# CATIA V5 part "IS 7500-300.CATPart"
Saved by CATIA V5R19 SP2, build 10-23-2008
Part number: IS 7500-300
Bounding box of the stored display mesh (mm): x -74.81 to 74.81, y -74.81 to 74.81, z 0 to 755
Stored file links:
  C:\Users\Bora\Desktop\3D Katı model\IS serisi\IS 7500\IS 7500-300.CATPart
  C:\Program Files\Dassault Systemes\B19\intel_a\reffiles\standard\MetricThinPitch.txt
  C:\Program Files\Dassault Systemes\B19\intel_a\reffiles\standard\MetricThickPitch.txt
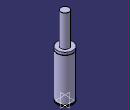
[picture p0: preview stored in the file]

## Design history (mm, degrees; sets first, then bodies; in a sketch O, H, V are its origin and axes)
Body1 (main body)
  Sketch1 on yz-plane, origin (0, 0, 0), H (0, 1, 0), V (0, 0, 1)
    point P1 (75, 430)
    point P2 (75, 425)
    point P5 (40, 754)
    point P7 (40, 754)
    point P12 (75, 425)
    point P13 (75, 430)
    arc A1 centre (75, 427.5) radius 2.5 from (75, 430) to (75, 425) ccw
    line L1 (75, 0) -> (75, 8)
    line L2 (40, 754) -> (40, 452)
    arc A2 centre (39, 754) radius 1 from (40, 754) to (39, 755) ccw
    line L3 (71, 15) -> (71, 8)
    line L4 (75, 15) -> (75, 425)
    line L5 (75, 430) -> (75, 452)
    line L6 (39, 755) -> (0, 755)
    point P15 (0, 755)
    line L7 (40, 452) -> (75, 452)
    line L8 (0, 0) -> (75, 0)
    line L9 (71, 8) -> (75, 8)
    line L10 (71, 15) -> (75, 15)
    coincidence: P15 V, P1 P13, P2 P12, P5 P7
    tangency: L6 A2
    horizontal: L7 H, L8 H, L9 H, L10 H
  Shaft1: profile Sketch1, axis Sketch1.V, angle 360
  Sketch2 on face of Shaft1 from Sketch1.L8, origin (0, 0, 0), H (1, 0, 0), V (0, -1, 0)
    point P1 (50, 0)
    distance P1 V = 50
  Hole1: placed by Sketch2, at (50, 0, 0) direction (0, 0, 1), diameter 8.376, depth 16, threaded "M10", thread diameter 10, thread depth 16, pitch 1.5
  CircPattern1: of Hole1, instances 4, angular step 90, axis from xy-plane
